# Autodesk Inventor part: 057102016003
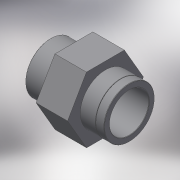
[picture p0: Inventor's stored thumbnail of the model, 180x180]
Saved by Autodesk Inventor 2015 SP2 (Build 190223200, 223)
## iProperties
Created: 2017-10
Part Number: 057102016003
Material: Generic
Description: PLASSON AD. SOCKET REINF.PVC 16-3/8"
Document SubType Name: Modeling
Designer: KIM
Density: 1 g/cm^3
Appearance: Default
Author: KIM
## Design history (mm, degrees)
derived "057102.ipt"
feature "Solid1::057102.ipt"
tag "TaggingFeature1"
body "Solid1"
other parameters: "d1" = 16, "d2" = 25, "d3" = 14.95, "d4" = 14.4, "d5" = 14, "d6" = 13, "d7" = 19.2, "d8" = 19.2, "d10" = 9.1, "d13" = 0, "d14" = 0.16, "d15" = 12, "d16" = 3.25, "d17" = 19.2, "d18" = 0.1, "d_" = 16, "G_" = 14.95, "C_" = 25, "B_" = 12, "l_" = 14, "lt_" = 13
